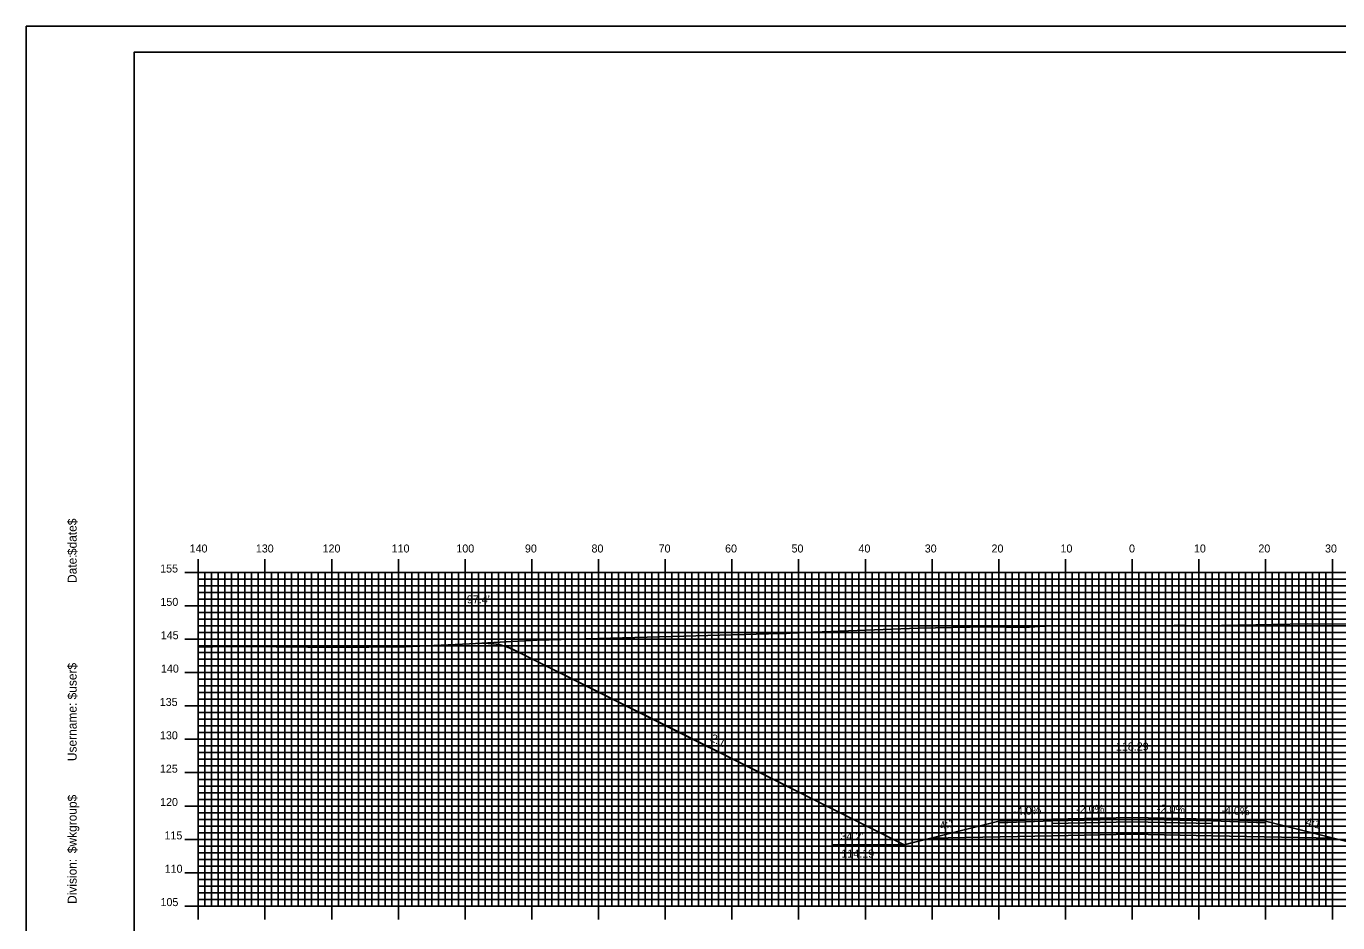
# Model space of a CAD drawing. Extents: x 1769268 to 1769611, y 442591 to 442811.
# Drawn here: x 1769267.7 to 1769464.3, y 442676.2 to 442810.5 of the extents above; entities that cross this region are included whole.
import ezdxf

# ---------------------------------------------------------------- set-up
doc = ezdxf.new("R2010")
doc.units = 0
for name, color, linetype in [('ANNOTATION', 7, 'Continuous'), ('BORDER', 7, 'Continuous'), ('D_Roadway_Centerline', 7, 'Continuous'), ('D_Roadway_Centerline_Text', 7, 'Continuous'), ('D_Roadway_Edge_Shoulder', 7, 'Continuous'), ('D_Roadway_Edge_TW', 7, 'Continuous'), ('D_Roadway_Pavement', 7, 'Continuous'), ('D_Roadway_SlopeLines', 7, 'Continuous'), ('D_Roadway_SubGrade', 7, 'Continuous'), ('D_Text_Standard', 7, 'Continuous'), ('H_V ANNOTATION', 7, 'Continuous'), ('MAJOR', 7, 'Continuous'), ('MINOR', 7, 'Continuous'), ('PDRAIN', 7, 'Continuous'), ('PLOT BOUNDARY', 7, 'Continuous'), ('S_Roadway_Centerline', 7, 'Continuous')]:
    doc.layers.add(name, color=color, linetype=linetype)

msp = doc.modelspace()

# ---------------------------------------------------------------- linework, layer by layer
at = {"layer": 'BORDER'}
msp.add_lwpolyline([(1769283.9, 442596.67), (1769603.9, 442596.67), (1769603.9, 442806.67), (1769283.9, 442806.67)], close=True, dxfattribs=at)
at = {"layer": 'D_Roadway_Centerline'}
msp.add_lwpolyline([(1769336.13, 442718.07), (1769336.94, 442718.05), (1769337.38, 442718.05), (1769337.73, 442717.99), (1769338.63, 442717.86), (1769339.75, 442717.53), (1769339.88, 442717.49), (1769340.19, 442717.36), (1769341.13, 442716.95), (1769365.57, 442704.73), (1769399.32, 442687.85), (1769399.33, 442687.85), (1769400.66, 442688.18), (1769403.33, 442688.85), (1769411.92, 442691), (1769413.5, 442691.4), (1769414.63, 442691.44), (1769421.5, 442691.72), (1769421.5, 442691.72), (1769433.5, 442691.96), (1769433.5, 442691.96), (1769445.5, 442691.72), (1769445.5, 442691.72), (1769445.5, 442691.72), (1769452.62, 442691.43), (1769453.5, 442691.4), (1769463.68, 442688.85), (1769466.33, 442688.19)], dxfattribs=at)
at = {"layer": 'D_Roadway_Edge_Shoulder'}
for points in [[(1769421.5, 442691.72), (1769413.5, 442691.4), (1769413.5, 442691.15), (1769421.5, 442691.47)], [(1769445.5, 442691.72), (1769453.5, 442691.4), (1769453.5, 442691.15), (1769445.5, 442691.47)]]:
    msp.add_lwpolyline(points, close=True, dxfattribs=at)
at = {"layer": 'D_Roadway_Edge_TW'}
msp.add_lwpolyline([(1769421.5, 442691.47), (1769421.5, 442691.72), (1769433.5, 442691.96), (1769445.5, 442691.72), (1769445.5, 442691.47), (1769433.5, 442691.71)], close=True, dxfattribs=at)
at = {"layer": 'D_Roadway_Pavement'}
msp.add_lwpolyline([(1769421.5, 442691.05), (1769421.5, 442691.47), (1769433.5, 442691.71), (1769445.5, 442691.47), (1769445.5, 442691.05), (1769433.5, 442691.29)], close=True, dxfattribs=at)
at = {"layer": 'D_Roadway_SlopeLines'}
for points in [[(1769399.33, 442687.85), (1769341.13, 442716.95), (1769339.88, 442717.49), (1769338.63, 442717.86), (1769337.38, 442718.05), (1769336.13, 442718.07)], [(1769413.5, 442691.4), (1769399.33, 442687.85)], [(1769453.5, 442691.4), (1769467.68, 442687.85)]]:
    msp.add_lwpolyline(points, dxfattribs=at)
at = {"layer": 'D_Roadway_SubGrade'}
msp.add_lwpolyline([(1769421.5, 442689.22), (1769403.33, 442688.85), (1769413.5, 442691.4), (1769413.5, 442691.15), (1769421.5, 442691.47), (1769433.5, 442691.71), (1769445.5, 442691.47), (1769453.5, 442691.15), (1769453.5, 442691.4), (1769463.68, 442688.85), (1769445.5, 442689.22), (1769433.5, 442689.46)], close=True, dxfattribs=at)
at = {"layer": 'MAJOR'}
for p, q in [((1769293.5, 442730.67), (1769293.5, 442728.67)), ((1769303.5, 442730.67), (1769303.5, 442728.67)), ((1769313.5, 442730.67), (1769313.5, 442728.67)), ((1769323.5, 442730.67), (1769323.5, 442728.67)), ((1769333.5, 442730.67), (1769333.5, 442728.67)), ((1769343.5, 442730.67), (1769343.5, 442728.67)), ((1769353.5, 442730.67), (1769353.5, 442728.67)), ((1769363.5, 442730.67), (1769363.5, 442728.67)), ((1769373.5, 442730.67), (1769373.5, 442728.67)), ((1769383.5, 442730.67), (1769383.5, 442728.67)), ((1769393.5, 442730.67), (1769393.5, 442728.67)), ((1769403.5, 442730.67), (1769403.5, 442728.67)), ((1769413.5, 442730.67), (1769413.5, 442728.67)), ((1769423.5, 442730.67), (1769423.5, 442728.67)), ((1769433.5, 442730.67), (1769433.5, 442728.67)), ((1769443.5, 442730.67), (1769443.5, 442728.67)), ((1769453.5, 442730.67), (1769453.5, 442728.67)), ((1769463.5, 442730.67), (1769463.5, 442728.67)), ((1769291.5, 442728.67), (1769293.5, 442728.67)), ((1769293.5, 442728.67), (1769573.5, 442728.67)), ((1769293.5, 442678.67), (1769293.5, 442728.67)), ((1769293.5, 442678.67), (1769293.5, 442728.67)), ((1769293.5, 442728.67), (1769573.5, 442728.67)), ((1769303.5, 442678.67), (1769303.5, 442728.67)), ((1769313.5, 442678.67), (1769313.5, 442728.67)), ((1769323.5, 442678.67), (1769323.5, 442728.67)), ((1769333.5, 442678.67), (1769333.5, 442728.67)), ((1769343.5, 442678.67), (1769343.5, 442728.67)), ((1769353.5, 442678.67), (1769353.5, 442728.67)), ((1769363.5, 442678.67), (1769363.5, 442728.67)), ((1769373.5, 442678.67), (1769373.5, 442728.67)), ((1769383.5, 442678.67), (1769383.5, 442728.67)), ((1769393.5, 442678.67), (1769393.5, 442728.67)), ((1769403.5, 442678.67), (1769403.5, 442728.67)), ((1769413.5, 442678.67), (1769413.5, 442728.67)), ((1769423.5, 442678.67), (1769423.5, 442728.67)), ((1769433.5, 442678.67), (1769433.5, 442728.67)), ((1769443.5, 442678.67), (1769443.5, 442728.67)), ((1769453.5, 442678.67), (1769453.5, 442728.67)), ((1769463.5, 442678.67), (1769463.5, 442728.67)), ((1769291.5, 442723.67), (1769293.5, 442723.67)), ((1769293.5, 442723.67), (1769573.5, 442723.67)), ((1769291.5, 442718.67), (1769293.5, 442718.67)), ((1769293.5, 442718.67), (1769573.5, 442718.67)), ((1769291.5, 442713.67), (1769293.5, 442713.67)), ((1769293.5, 442713.67), (1769573.5, 442713.67)), ((1769291.5, 442708.67), (1769293.5, 442708.67)), ((1769293.5, 442708.67), (1769573.5, 442708.67)), ((1769291.5, 442703.67), (1769293.5, 442703.67)), ((1769293.5, 442703.67), (1769573.5, 442703.67)), ((1769291.5, 442698.67), (1769293.5, 442698.67)), ((1769293.5, 442698.67), (1769573.5, 442698.67)), ((1769291.5, 442693.67), (1769293.5, 442693.67)), ((1769293.5, 442693.67), (1769573.5, 442693.67)), ((1769291.5, 442688.67), (1769293.5, 442688.67)), ((1769293.5, 442688.67), (1769573.5, 442688.67)), ((1769291.5, 442683.67), (1769293.5, 442683.67)), ((1769293.5, 442683.67), (1769573.5, 442683.67)), ((1769291.5, 442678.67), (1769293.5, 442678.67)), ((1769293.5, 442678.67), (1769573.5, 442678.67)), ((1769293.5, 442678.67), (1769573.5, 442678.67)), ((1769293.5, 442676.66), (1769293.5, 442678.67)), ((1769303.5, 442676.66), (1769303.5, 442678.67)), ((1769313.5, 442676.66), (1769313.5, 442678.67)), ((1769323.5, 442676.66), (1769323.5, 442678.67)), ((1769333.5, 442676.66), (1769333.5, 442678.67)), ((1769343.5, 442676.66), (1769343.5, 442678.67)), ((1769353.5, 442676.66), (1769353.5, 442678.67)), ((1769363.5, 442676.66), (1769363.5, 442678.67)), ((1769373.5, 442676.66), (1769373.5, 442678.67)), ((1769383.5, 442676.66), (1769383.5, 442678.67)), ((1769393.5, 442676.66), (1769393.5, 442678.67)), ((1769403.5, 442676.66), (1769403.5, 442678.67)), ((1769413.5, 442676.66), (1769413.5, 442678.67)), ((1769423.5, 442676.66), (1769423.5, 442678.67)), ((1769433.5, 442676.66), (1769433.5, 442678.67)), ((1769443.5, 442676.66), (1769443.5, 442678.67)), ((1769453.5, 442676.66), (1769453.5, 442678.67)), ((1769463.5, 442676.66), (1769463.5, 442678.67))]:
    msp.add_line(p, q, dxfattribs=at)
at = {"layer": 'MINOR'}
for p, q in [((1769293.5, 442727.67), (1769573.5, 442727.67)), ((1769293.5, 442727.67), (1769295.51, 442727.67)), ((1769294.5, 442678.67), (1769294.5, 442728.67)), ((1769295.5, 442678.67), (1769295.5, 442728.67)), ((1769296.5, 442678.67), (1769296.5, 442728.67)), ((1769297.5, 442678.67), (1769297.5, 442728.67)), ((1769298.5, 442678.67), (1769298.5, 442728.67)), ((1769299.5, 442678.67), (1769299.5, 442728.67)), ((1769300.5, 442678.67), (1769300.5, 442728.67)), ((1769301.5, 442678.67), (1769301.5, 442728.67)), ((1769302.5, 442678.67), (1769302.5, 442728.67)), ((1769304.5, 442678.67), (1769304.5, 442728.67)), ((1769305.5, 442678.67), (1769305.5, 442728.67)), ((1769306.5, 442678.67), (1769306.5, 442728.67)), ((1769307.5, 442678.67), (1769307.5, 442728.67)), ((1769308.5, 442678.67), (1769308.5, 442728.67)), ((1769309.5, 442678.67), (1769309.5, 442728.67)), ((1769310.5, 442678.67), (1769310.5, 442728.67)), ((1769311.5, 442678.67), (1769311.5, 442728.67)), ((1769312.5, 442678.67), (1769312.5, 442728.67)), ((1769314.5, 442678.67), (1769314.5, 442728.67)), ((1769315.5, 442678.67), (1769315.5, 442728.67)), ((1769316.5, 442678.67), (1769316.5, 442728.67)), ((1769317.5, 442678.67), (1769317.5, 442728.67)), ((1769318.5, 442678.67), (1769318.5, 442728.67)), ((1769319.5, 442678.67), (1769319.5, 442728.67)), ((1769320.5, 442678.67), (1769320.5, 442728.67)), ((1769321.5, 442678.67), (1769321.5, 442728.67)), ((1769322.5, 442678.67), (1769322.5, 442728.67)), ((1769324.5, 442678.67), (1769324.5, 442728.67)), ((1769325.5, 442678.67), (1769325.5, 442728.67)), ((1769326.5, 442678.67), (1769326.5, 442728.67)), ((1769327.5, 442678.67), (1769327.5, 442728.67)), ((1769328.5, 442678.67), (1769328.5, 442728.67)), ((1769329.5, 442678.67), (1769329.5, 442728.67)), ((1769330.5, 442678.67), (1769330.5, 442728.67)), ((1769331.5, 442678.67), (1769331.5, 442728.67)), ((1769332.5, 442678.67), (1769332.5, 442728.67)), ((1769334.5, 442678.67), (1769334.5, 442728.67)), ((1769335.5, 442678.67), (1769335.5, 442728.67)), ((1769336.5, 442678.67), (1769336.5, 442728.67)), ((1769337.5, 442678.67), (1769337.5, 442728.67)), ((1769338.5, 442678.67), (1769338.5, 442728.67)), ((1769339.5, 442678.67), (1769339.5, 442728.67)), ((1769340.5, 442678.67), (1769340.5, 442728.67)), ((1769341.5, 442678.67), (1769341.5, 442728.67)), ((1769342.5, 442678.67), (1769342.5, 442728.67)), ((1769344.5, 442678.67), (1769344.5, 442728.67)), ((1769345.5, 442678.67), (1769345.5, 442728.67)), ((1769346.5, 442678.67), (1769346.5, 442728.67)), ((1769347.5, 442678.67), (1769347.5, 442728.67)), ((1769348.5, 442678.67), (1769348.5, 442728.67)), ((1769349.5, 442678.67), (1769349.5, 442728.67)), ((1769350.5, 442678.67), (1769350.5, 442728.67)), ((1769351.5, 442678.67), (1769351.5, 442728.67)), ((1769352.5, 442678.67), (1769352.5, 442728.67)), ((1769354.5, 442678.67), (1769354.5, 442728.67)), ((1769355.5, 442678.67), (1769355.5, 442728.67)), ((1769356.5, 442678.67), (1769356.5, 442728.67)), ((1769357.5, 442678.67), (1769357.5, 442728.67)), ((1769358.5, 442678.67), (1769358.5, 442728.67)), ((1769359.5, 442678.67), (1769359.5, 442728.67)), ((1769360.5, 442678.67), (1769360.5, 442728.67)), ((1769361.5, 442678.67), (1769361.5, 442728.67)), ((1769362.5, 442678.67), (1769362.5, 442728.67)), ((1769364.5, 442678.67), (1769364.5, 442728.67)), ((1769365.5, 442678.67), (1769365.5, 442728.67)), ((1769366.5, 442678.67), (1769366.5, 442728.67)), ((1769367.5, 442678.67), (1769367.5, 442728.67)), ((1769368.5, 442678.67), (1769368.5, 442728.67)), ((1769369.5, 442678.67), (1769369.5, 442728.67)), ((1769370.5, 442678.67), (1769370.5, 442728.67)), ((1769371.5, 442678.67), (1769371.5, 442728.67)), ((1769372.5, 442678.67), (1769372.5, 442728.67)), ((1769374.5, 442678.67), (1769374.5, 442728.67)), ((1769375.5, 442678.67), (1769375.5, 442728.67)), ((1769376.5, 442678.67), (1769376.5, 442728.67)), ((1769377.5, 442678.67), (1769377.5, 442728.67)), ((1769378.5, 442678.67), (1769378.5, 442728.67)), ((1769379.5, 442678.67), (1769379.5, 442728.67)), ((1769380.5, 442678.67), (1769380.5, 442728.67)), ((1769381.5, 442678.67), (1769381.5, 442728.67)), ((1769382.5, 442678.67), (1769382.5, 442728.67)), ((1769384.5, 442678.67), (1769384.5, 442728.67)), ((1769385.5, 442678.67), (1769385.5, 442728.67)), ((1769386.5, 442678.67), (1769386.5, 442728.67)), ((1769387.5, 442678.67), (1769387.5, 442728.67)), ((1769388.5, 442678.67), (1769388.5, 442728.67)), ((1769389.5, 442678.67), (1769389.5, 442728.67)), ((1769390.5, 442678.67), (1769390.5, 442728.67)), ((1769391.5, 442678.67), (1769391.5, 442728.67)), ((1769392.5, 442678.67), (1769392.5, 442728.67)), ((1769394.5, 442678.67), (1769394.5, 442728.67)), ((1769395.5, 442678.67), (1769395.5, 442728.67)), ((1769396.5, 442678.67), (1769396.5, 442728.67)), ((1769397.5, 442678.67), (1769397.5, 442728.67)), ((1769398.5, 442678.67), (1769398.5, 442728.67)), ((1769399.5, 442678.67), (1769399.5, 442728.67)), ((1769400.5, 442678.67), (1769400.5, 442728.67)), ((1769401.5, 442678.67), (1769401.5, 442728.67)), ((1769402.5, 442678.67), (1769402.5, 442728.67)), ((1769404.5, 442678.67), (1769404.5, 442728.67)), ((1769405.5, 442678.67), (1769405.5, 442728.67)), ((1769406.5, 442678.67), (1769406.5, 442728.67)), ((1769407.5, 442678.67), (1769407.5, 442728.67)), ((1769408.5, 442678.67), (1769408.5, 442728.67)), ((1769409.5, 442678.67), (1769409.5, 442728.67)), ((1769410.5, 442678.67), (1769410.5, 442728.67)), ((1769411.5, 442678.67), (1769411.5, 442728.67)), ((1769412.5, 442678.67), (1769412.5, 442728.67)), ((1769414.5, 442678.67), (1769414.5, 442728.67)), ((1769415.5, 442678.67), (1769415.5, 442728.67)), ((1769416.5, 442678.67), (1769416.5, 442728.67)), ((1769417.5, 442678.67), (1769417.5, 442728.67)), ((1769418.5, 442678.67), (1769418.5, 442728.67)), ((1769419.5, 442678.67), (1769419.5, 442728.67)), ((1769420.5, 442678.67), (1769420.5, 442728.67)), ((1769421.5, 442678.67), (1769421.5, 442728.67)), ((1769422.5, 442678.67), (1769422.5, 442728.67)), ((1769424.5, 442678.67), (1769424.5, 442728.67)), ((1769425.5, 442678.67), (1769425.5, 442728.67)), ((1769426.5, 442678.67), (1769426.5, 442728.67)), ((1769427.5, 442678.67), (1769427.5, 442728.67)), ((1769428.5, 442678.67), (1769428.5, 442728.67)), ((1769429.5, 442678.67), (1769429.5, 442728.67)), ((1769430.5, 442678.67), (1769430.5, 442728.67)), ((1769431.5, 442678.67), (1769431.5, 442728.67)), ((1769432.5, 442678.67), (1769432.5, 442728.67)), ((1769434.5, 442678.67), (1769434.5, 442728.67)), ((1769435.5, 442678.67), (1769435.5, 442728.67)), ((1769436.5, 442678.67), (1769436.5, 442728.67)), ((1769437.5, 442678.67), (1769437.5, 442728.67)), ((1769438.5, 442678.67), (1769438.5, 442728.67)), ((1769439.5, 442678.67), (1769439.5, 442728.67)), ((1769440.5, 442678.67), (1769440.5, 442728.67)), ((1769441.5, 442678.67), (1769441.5, 442728.67)), ((1769442.5, 442678.67), (1769442.5, 442728.67)), ((1769444.5, 442678.67), (1769444.5, 442728.67)), ((1769445.5, 442678.67), (1769445.5, 442728.67)), ((1769446.5, 442678.67), (1769446.5, 442728.67)), ((1769447.5, 442678.67), (1769447.5, 442728.67)), ((1769448.5, 442678.67), (1769448.5, 442728.67)), ((1769449.5, 442678.67), (1769449.5, 442728.67)), ((1769450.5, 442678.67), (1769450.5, 442728.67)), ((1769451.5, 442678.67), (1769451.5, 442728.67)), ((1769452.5, 442678.67), (1769452.5, 442728.67)), ((1769454.5, 442678.67), (1769454.5, 442728.67)), ((1769455.5, 442678.67), (1769455.5, 442728.67)), ((1769456.5, 442678.67), (1769456.5, 442728.67)), ((1769457.5, 442678.67), (1769457.5, 442728.67)), ((1769458.5, 442678.67), (1769458.5, 442728.67)), ((1769459.5, 442678.67), (1769459.5, 442728.67)), ((1769460.5, 442678.67), (1769460.5, 442728.67)), ((1769461.5, 442678.67), (1769461.5, 442728.67)), ((1769462.5, 442678.67), (1769462.5, 442728.67)), ((1769293.5, 442726.67), (1769573.5, 442726.67)), ((1769293.5, 442726.67), (1769295.51, 442726.67)), ((1769293.5, 442725.67), (1769573.5, 442725.67)), ((1769293.5, 442725.67), (1769295.51, 442725.67)), ((1769293.5, 442724.67), (1769573.5, 442724.67)), ((1769293.5, 442724.67), (1769295.51, 442724.67)), ((1769293.5, 442722.67), (1769573.5, 442722.67)), ((1769293.5, 442722.67), (1769295.51, 442722.67)), ((1769293.5, 442721.67), (1769573.5, 442721.67)), ((1769293.5, 442721.67), (1769295.51, 442721.67)), ((1769293.5, 442720.67), (1769573.5, 442720.67)), ((1769293.5, 442720.67), (1769295.51, 442720.67)), ((1769293.5, 442719.67), (1769573.5, 442719.67)), ((1769293.5, 442719.67), (1769295.51, 442719.67)), ((1769293.5, 442717.67), (1769573.5, 442717.67)), ((1769293.5, 442717.67), (1769295.51, 442717.67)), ((1769293.5, 442716.67), (1769573.5, 442716.67)), ((1769293.5, 442716.67), (1769295.51, 442716.67)), ((1769293.5, 442715.67), (1769573.5, 442715.67)), ((1769293.5, 442715.67), (1769295.51, 442715.67)), ((1769293.5, 442714.67), (1769573.5, 442714.67)), ((1769293.5, 442714.67), (1769295.51, 442714.67)), ((1769293.5, 442712.67), (1769573.5, 442712.67)), ((1769293.5, 442712.67), (1769295.51, 442712.67)), ((1769293.5, 442711.67), (1769573.5, 442711.67)), ((1769293.5, 442711.67), (1769295.51, 442711.67)), ((1769293.5, 442710.67), (1769573.5, 442710.67)), ((1769293.5, 442710.67), (1769295.51, 442710.67)), ((1769293.5, 442709.67), (1769573.5, 442709.67)), ((1769293.5, 442709.67), (1769295.51, 442709.67)), ((1769293.5, 442707.67), (1769573.5, 442707.67)), ((1769293.5, 442707.67), (1769295.51, 442707.67)), ((1769293.5, 442706.67), (1769573.5, 442706.67)), ((1769293.5, 442706.67), (1769295.51, 442706.67)), ((1769293.5, 442705.67), (1769573.5, 442705.67)), ((1769293.5, 442705.67), (1769295.51, 442705.67)), ((1769293.5, 442704.67), (1769573.5, 442704.67)), ((1769293.5, 442704.67), (1769295.51, 442704.67)), ((1769293.5, 442702.67), (1769573.5, 442702.67)), ((1769293.5, 442702.67), (1769295.51, 442702.67)), ((1769293.5, 442701.67), (1769573.5, 442701.67)), ((1769293.5, 442701.67), (1769295.51, 442701.67)), ((1769293.5, 442700.67), (1769573.5, 442700.67)), ((1769293.5, 442700.67), (1769295.51, 442700.67)), ((1769293.5, 442699.67), (1769573.5, 442699.67)), ((1769293.5, 442699.67), (1769295.51, 442699.67)), ((1769293.5, 442697.67), (1769573.5, 442697.67)), ((1769293.5, 442697.67), (1769295.51, 442697.67)), ((1769293.5, 442696.67), (1769573.5, 442696.67)), ((1769293.5, 442696.67), (1769295.51, 442696.67)), ((1769293.5, 442695.67), (1769573.5, 442695.67)), ((1769293.5, 442695.67), (1769295.51, 442695.67)), ((1769293.5, 442694.67), (1769573.5, 442694.67)), ((1769293.5, 442694.67), (1769295.51, 442694.67)), ((1769293.5, 442692.67), (1769573.5, 442692.67)), ((1769293.5, 442692.67), (1769295.51, 442692.67)), ((1769293.5, 442691.67), (1769573.5, 442691.67)), ((1769293.5, 442691.67), (1769295.51, 442691.67)), ((1769293.5, 442690.67), (1769573.5, 442690.67)), ((1769293.5, 442690.67), (1769295.51, 442690.67)), ((1769293.5, 442689.67), (1769573.5, 442689.67)), ((1769293.5, 442689.67), (1769295.51, 442689.67)), ((1769293.5, 442687.67), (1769573.5, 442687.67)), ((1769293.5, 442687.67), (1769295.51, 442687.67)), ((1769293.5, 442686.67), (1769573.5, 442686.67)), ((1769293.5, 442686.67), (1769295.51, 442686.67)), ((1769293.5, 442685.67), (1769573.5, 442685.67)), ((1769293.5, 442685.67), (1769295.51, 442685.67)), ((1769293.5, 442684.67), (1769573.5, 442684.67)), ((1769293.5, 442684.67), (1769295.51, 442684.67)), ((1769293.5, 442682.67), (1769573.5, 442682.67)), ((1769293.5, 442682.67), (1769295.51, 442682.67)), ((1769293.5, 442681.67), (1769573.5, 442681.67)), ((1769293.5, 442681.67), (1769295.51, 442681.67)), ((1769293.5, 442680.67), (1769573.5, 442680.67)), ((1769293.5, 442680.67), (1769295.51, 442680.67)), ((1769293.5, 442679.67), (1769573.5, 442679.67)), ((1769293.5, 442679.67), (1769295.51, 442679.67))]:
    msp.add_line(p, q, dxfattribs=at)
at = {"layer": 'PDRAIN'}
msp.add_line((1769388.6, 442687.85), (1769399.33, 442687.85), dxfattribs=at)
at = {"layer": 'PLOT BOUNDARY'}
msp.add_lwpolyline([(1769267.72, 442590.55), (1769607.72, 442590.55), (1769607.72, 442810.55), (1769267.72, 442810.55)], close=True, dxfattribs=at)
at = {"layer": 'S_Roadway_Centerline'}
msp.add_lwpolyline([(1769293.5, 442717.47), (1769297.9, 442717.6), (1769305.2, 442717.53), (1769309.92, 442717.5), (1769319.05, 442717.46), (1769322.57, 442717.52), (1769324.59, 442717.55), (1769334.17, 442717.96), (1769344.26, 442718.51), (1769349.73, 442718.68), (1769362.66, 442719.05), (1769380.76, 442719.51), (1769381.67, 442719.55), (1769382.23, 442719.56), (1769384.45, 442719.66), (1769401.42, 442720.32), (1769411.83, 442720.53), (1769417.37, 442720.43), (1769420.47, 442720.64), (1769433.1, 442720.69), (1769439.8, 442720.73), (1769441.54, 442720.72), (1769444.3, 442720.68), (1769459.72, 442720.96), (1769474.26, 442720.88)], dxfattribs=at)

# ---------------------------------------------------------------- texts
at = {"layer": 'ANNOTATION'}
for s, rotation, p in [('2:1', 333.4352, (1769370.16, 442703.47)), ('-4.0%', 2.2905, (1769415.7, 442692.29)), ('-2.0%', 1.1457, (1769425.11, 442692.59)), ('-2.0%', 358.8542, (1769437.19, 442692.68)), ('-4.0%', 357.7094, (1769446.86, 442692.46)), ('4:1', 14.0388, (1769404.82, 442690.09)), ('4:1', 345.9614, (1769459.42, 442690.78))]:
    msp.add_text(s, height=1.2, rotation=rotation, dxfattribs=at).set_placement(p)
for s, p in [("34.2'", (1769389.77, 442688.54)), ('114.19', (1769389.9, 442685.94))]:
    msp.add_text(s, height=1.2, dxfattribs=at).set_placement(p)
at = {"layer": 'BORDER'}
for s, p in [('$date$', (1769275.27, 442731.28)), ('Date:', (1769275.27, 442727.1)), ('$user$', (1769275.27, 442709.65)), ('Username:', (1769275.27, 442700.4)), ('$wkgroup$', (1769275.27, 442686.6)), ('Division:', (1769275.27, 442679))]:
    msp.add_text(s, height=1.339, rotation=90, dxfattribs=at).set_placement(p)
at = {"layer": 'D_Roadway_Centerline'}
for s, p in [('C', (1769433.5, 442691.96)), ('L', (1769433.5, 442691.95))]:
    msp.add_text(s, height=0.0146, dxfattribs=at).set_placement(p)
at = {"layer": 'D_Roadway_Centerline_Text'}
msp.add_text('118.29', height=1.2, dxfattribs=at).set_placement((1769431.06, 442701.99))
at = {"layer": 'D_Text_Standard'}
msp.add_text("97.4'", height=1.2, dxfattribs=at).set_placement((1769333.77, 442724.05))
at = {"layer": 'H_V ANNOTATION'}
for s, p in [('140', (1769292.21, 442731.67)), ('130', (1769302.13, 442731.67)), ('120', (1769312.14, 442731.67)), ('110', (1769322.49, 442731.67)), ('100', (1769332.19, 442731.67)), ('90', (1769342.47, 442731.67)), ('80', (1769352.45, 442731.67)), ('70', (1769362.51, 442731.67)), ('60', (1769372.47, 442731.67)), ('50', (1769382.43, 442731.67)), ('40', (1769392.47, 442731.67)), ('30', (1769402.4, 442731.67)), ('20', (1769412.41, 442731.67)), ('10', (1769422.75, 442731.67)), ('0', (1769433.02, 442731.67)), ('10', (1769442.75, 442731.67)), ('20', (1769452.41, 442731.67)), ('30', (1769462.4, 442731.67)), ('155', (1769287.79, 442728.67)), ('150', (1769287.83, 442723.67)), ('145', (1769287.88, 442718.67)), ('140', (1769287.91, 442713.67)), ('135', (1769287.73, 442708.67)), ('130', (1769287.76, 442703.67)), ('125', (1769287.75, 442698.67)), ('120', (1769287.78, 442693.67)), ('115', (1769288.44, 442688.67)), ('110', (1769288.47, 442683.67)), ('105', (1769287.84, 442678.67))]:
    msp.add_text(s, height=1.2, dxfattribs=at).set_placement(p)
at = {"layer": 'MAJOR'}
msp.add_text('-', height=0.012, dxfattribs=at).set_placement((1769293.49, 442678.67))

doc.saveas('drawing.dxf')
